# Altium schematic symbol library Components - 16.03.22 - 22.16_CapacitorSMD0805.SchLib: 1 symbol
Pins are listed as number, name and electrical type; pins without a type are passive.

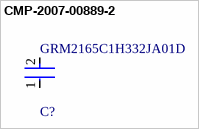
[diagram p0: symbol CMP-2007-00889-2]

## CMP-2007-00889-2
designator C?, comment GRM2165C1H332JA01D
Chip Multilayer Ceramic Capacitors for General Purpose, 0805, 3300pF, C0G, 30ppm/°C, 5%, 50V; Insulation Resistance: 10GR; Capacitance: 3.3nF
footprint FP-GRM216-0_1-IPC_A
footprint FP-GRM216-0_1-IPC_C
footprint FP-GRM216-0_1-MFG
footprint FP-GRM216-0_1-IPC_B
pins: 1, 2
